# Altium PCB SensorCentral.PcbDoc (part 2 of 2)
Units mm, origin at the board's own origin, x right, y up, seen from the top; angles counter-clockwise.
Board outline 99.21 x 99.07 mm, 6 copper layers (Top Layer 1, GND1, Signal, GND2, GND3, Bottom Layer 1), stack 1.538 mm thick; 91 components, 67 nets, 452 pads, 462 vias.
Unrouted connection lines stored in the file: 278.
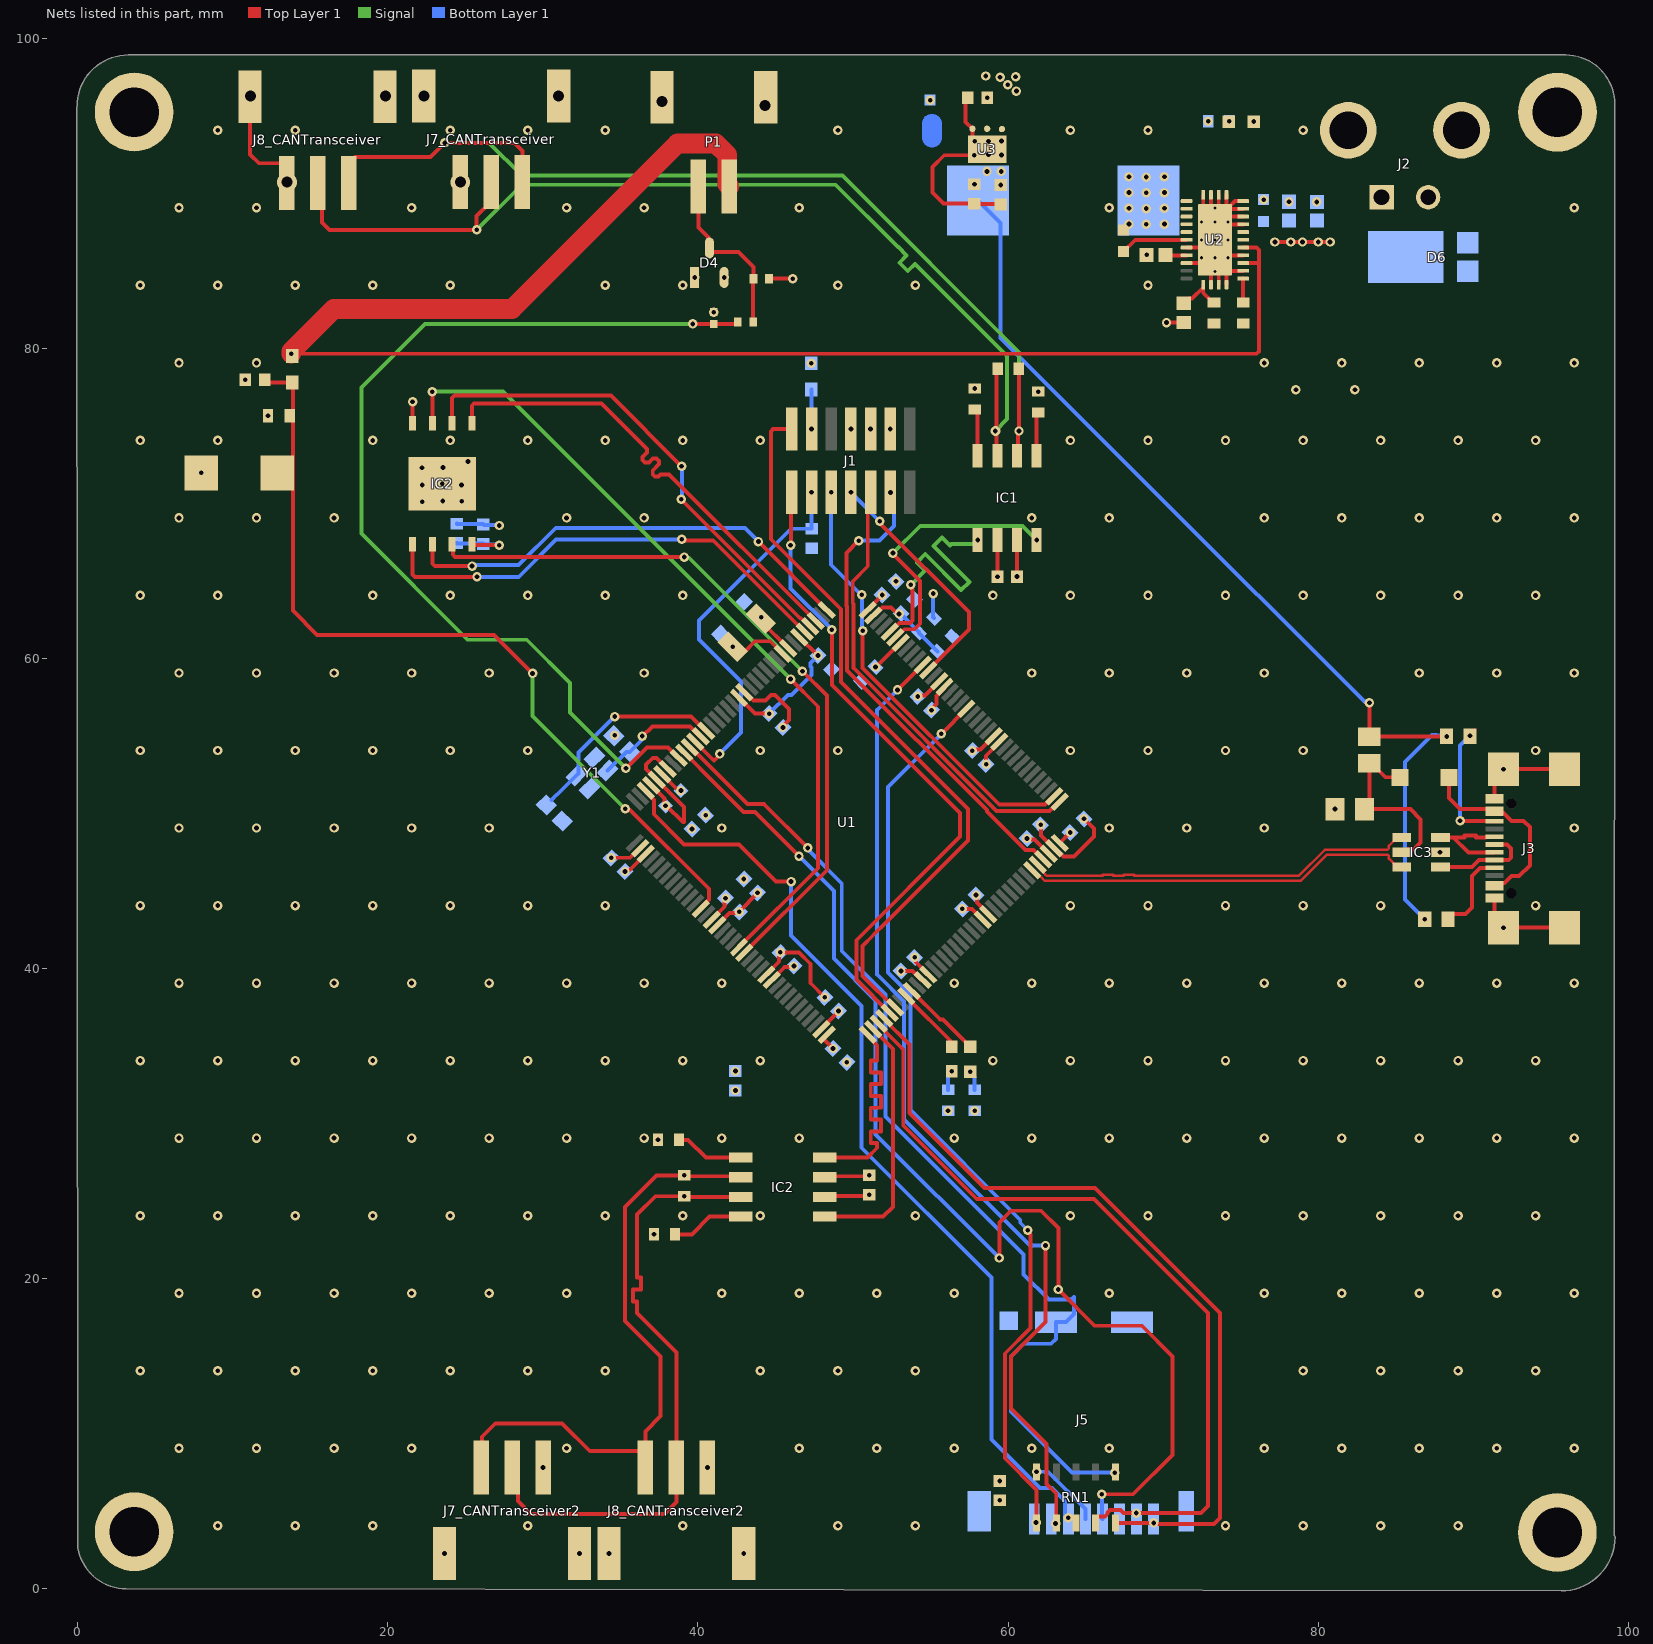
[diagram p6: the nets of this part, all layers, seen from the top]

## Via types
v1: diameter 0.61, hole 0.305, Top Layer 1 to Bottom Layer 1, tented both sides, 441 vias
v2: diameter 0.5, hole 0.2, Top Layer 1 to Bottom Layer 1, 11 vias
v3: diameter 1.27, hole 0.711, Top Layer 1 to Bottom Layer 1, tented both sides, 8 vias
v4: diameter 0.61, hole 0.33, Top Layer 1 to Bottom Layer 1, tented both sides, 1 vias
v5: diameter 0.65, hole 0.305, Top Layer 1 to Bottom Layer 1, tented both sides, 1 vias

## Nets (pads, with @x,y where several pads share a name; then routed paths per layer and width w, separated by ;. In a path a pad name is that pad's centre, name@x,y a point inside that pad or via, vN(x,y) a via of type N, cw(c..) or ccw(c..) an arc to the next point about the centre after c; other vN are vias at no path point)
5V: C8.1 D7.1 FB1.2 IC3.5 | length 11.9
  Top Layer 1 w0.254: FB1.2@83.312,53.252 83.312,50.612 C8.1@82.992,50.292 85.952,50.292 86.614,49.63 86.614,48.128 86.16,47.674 85.56,47.674 IC3.5@85.395,47.508 ; FB1.2@83.437,53.252 84.347,52.342 D7.1@85.007,52.342
ADC1_INP2: C36.1 D5.1 R12.1 R13.2 U1.49 | length 55.5
  Top Layer 1 w0.254: C36.1@12.057,77.978 12.23,77.805 13.937,77.805 13.944,77.797 13.868,77.721 13.868,72.984 D5.1@12.864,71.98 ; D5.1@13.876,73.011 13.876,63.095 15.442,61.53 26.843,61.53 v1(29.332,59.041) ; v1(35.307,50.313) 35.375,50.245 35.607,50.245 40.699,45.153 40.699,44.453 40.17,43.924 U1.49@40.17,43.862
  Signal w0.254: v1(29.332,59.041) 29.332,56.289 v1(35.307,50.313)
AN_P_PRESSURE_NOSE: C7.1 R8.2 U1.28 | length 64.1
  Top Layer 1 w0.254: v1(35.353,52.917) 36.712,54.276 38.065,54.276 U1.28@38.756,53.585 ; v1(39.672,81.582) C7.1@41.027,81.582 42.436,81.582 R8.2@42.559,81.706 R8.2@42.559,81.706
  Signal w0.254: v1(35.353,52.917) 31.75,56.52 31.75,58.42 28.956,61.214 25.146,61.214 18.288,68.072 18.288,77.47 22.4,81.582 v1(39.672,81.582)
BOOT0: R2.2 U1.138 | length 2.3
  Top Layer 1 w0.254: v1(51.455,59.456) 51.489,59.456 53.042,61.009 U1.138@53.075,61.009
CANH_CANTransceiver: IC1.7 J7_CANTransceiver.2 J8_CANTransceiver.2 R16.1 | length 68.6
  Top Layer 1 w0.254: J8_CANTransceiver.2@15.494,90.73 15.748,90.476 15.748,88.138 16.236,87.65 v1(25.728,87.65) 25.728,88.538 26.67,89.48 J7_CANTransceiver.2@26.67,90.73 ; IC1.7@59.309,73.07 59.245,73.134 59.245,74.612 v5(59.182,74.676) 59.258,74.752 59.258,78.619 R16.1@59.334,78.695
  Signal w0.254: v1(25.728,87.65) 28.639,90.561 48.885,90.561 52.826,86.62 52.916,86.53 52.925,86.539 53.463,86 52.992,85.528 53.531,84.99 53.993,85.453 54.149,85.297 59.944,79.502 59.944,75.438 v5(59.182,74.676)
CANH_CANTransceiver2: IC2.7@42.754,25.273 J7_CANTransceiver2.2 J8_CANTransceiver2.2 R16_CANTransceiver2.1 | length 41
  Top Layer 1 w0.254: J7_CANTransceiver2.2@28.008,7.822 28.381,7.449 28.381,5.655 29.21,4.826 37.846,4.826 38.608,5.588 J8_CANTransceiver2.2@38.608,7.822 38.608,15.24 36.068,17.78 36.068,18.415 36.068,18.542 35.814,18.542 35.814,19.304 36.32,19.304 36.32,20.066 36.068,20.066 36.068,20.442 36.068,24.13 37.255,25.317 v1(39.116,25.317) 39.16,25.273 IC2.7@42.754,25.273
CANL_CANTransceiver: IC1.6 J7_CANTransceiver.3 J8_CANTransceiver.3 R16.2 | length 68.6
  Top Layer 1 w0.254: J8_CANTransceiver.3@17.494,90.73 17.494,91.98 17.867,92.353 22.76,92.353 v1(23.663,93.256) 28.156,93.256 28.67,92.742 J7_CANTransceiver.3@28.67,90.73 ; IC1.6@60.579,73.07 60.642,73.134 60.642,74.612 v1(60.706,74.676) 60.697,74.685 60.697,78.686 R16.2@60.688,78.695
  Signal w0.254: v1(23.663,93.256) 26.535,93.256 28.646,91.145 49.317,91.145 60.706,79.756 v1(60.706,74.676)
CANL_CANTransceiver2: IC2.6@42.754,26.543 J7_CANTransceiver2.3 J8_CANTransceiver2.3 R16_CANTransceiver2.2 | length 41
  Top Layer 1 w0.254: J7_CANTransceiver2.3@26.008,7.822 26.06,7.874 26.06,9.804 26.924,10.668 31.242,10.668 33.02,8.89 36.235,8.89 36.608,8.517 J8_CANTransceiver2.3@36.608,7.822 36.608,10.157 37.592,11.141 37.592,14.986 35.306,17.272 35.306,24.638 37.338,26.67 v1(39.116,26.67) 39.179,26.606 42.69,26.606 IC2.6@42.754,26.543
CARD_DETECT: J5.10 RN1.6 U1.26 | length 66.4
  Top Layer 1 w0.254: U1.26@39.463,54.292 39.525,54.292 43.192,50.625 44.246,50.625 v1(47.087,47.783)
  Bottom Layer 1 w0.254: v1(47.087,47.783) 47.087,47.687 49.276,45.498 49.276,41.148 52.094,38.33 52.094,30.459 61,21.553 61,20.28 62.633,18.647 64.074,18.647 64.262,18.835 64.262,17.723 63.738,17.199 J5.10@63.088,17.199 63.088,16.118 62.774,15.804 61.011,15.804 60.198,14.991 60.198,11.43 64.139,7.489 v1(66.882,7.489)
CC1: J3.A5 R18.2 | length 5.6
  Top Layer 1 w0.254: R18.2@88.38,43.18 88.38,43.221 88.678,43.519 89.493,43.519 89.916,43.942 89.916,45.974 90.444,46.502 J3.A5@91.381,46.502
CC2: J3.B5 R19.1 | length 8.5
  Top Layer 1 w0.254: v1@89.155,49.529 90.809,49.529 90.813,49.525 91.356,49.525 J3.B5@91.38,49.501 ; R19.1@89.789,54.977 89.789,55.052 R19.1@90.087,55.35
  Bottom Layer 1 w0.254: v1(89.154,49.53) 89.154,54.379 v1(89.789,55.015)
CD/DAT3: J5.2 RN1.2 U1.134 | length 63.8
  Top Layer 1 w0.254: v1(52.869,57.975) U1.134@54.489,59.595 ; v1(62.417,22.138) 62.417,17.211 60.198,14.991 60.198,11.63 62.489,9.339 62.489,6.759 63.11,6.137 63.11,4.256 v1(63.066,4.212)
  Bottom Layer 1 w0.254: v1(52.869,57.975) 51.562,56.669 51.562,39.612 53.289,37.886 53.289,30.277 61.428,22.138 v1(62.417,22.138)
CL_PRESSURE_NOSE: D4.3 P1.2 R8.1 R17.1 | length 10.9
  Top Layer 1 w0.254: P1.2@40.027,90.194 40.027,87.812 40.677,87.162 40.677,86.544 D4.3@40.738,86.483 ; D4.3@40.738,86.365 40.885,86.218 42.612,86.218 43.575,85.254 R17.1@43.575,84.5 ; R17.1@43.55,84.5 43.55,83.289 43.559,83.28 R8.1@43.559,81.706
CLK: J5.5 U1.27 | length 75
  Top Layer 1 w0.254: U1.27@39.11,53.938 40.157,52.891 40.157,52.875 42.934,50.098 43.671,50.098 v1(46.517,47.252) ; v1(59.436,21.336) 59.436,23.622 60.198,24.384 62.127,24.384 63.246,23.265 v1(63.246,19.304) 65.583,16.967 68.631,16.967 70.612,14.986 70.612,8.636 68.072,6.096 v1(66.04,6.096)
  Bottom Layer 1 w0.254: v1(46.517,47.252) 48.768,45.001 48.768,40.64 51.46,37.948 51.46,29.312 v1(59.436,21.336) ; v1(66.04,6.096) 66.064,6.072 66.064,4.523 J5.5@66.088,4.499
CMD: J5.3 RN1.3 U1.34 | length 62
  Top Layer 1 w0.254: U1.34@36.635,51.464 36.635,51.401 37.163,50.873 37.163,49.959 39.108,48.014 42.644,48.014 45.042,45.616 v1(46.007,45.616) ; v1(63.882,4.58) 64.282,4.58 64.38,4.482 RN1.3@64.38,4.247
  Bottom Layer 1 w0.254: v1(46.007,45.616) 46.007,42.131 50.546,37.592 50.546,28.448 58.928,20.066 58.928,9.633 61.255,7.307 61.255,7.304 61.598,6.961 61.6,6.961 62.072,6.489 62.833,6.489 63.665,5.656 63.665,4.797 v1(63.882,4.58)
CS: IC2.1@25.412,75.176 U1.3 | length 31.4
  Top Layer 1 w0.254: IC2.1@25.412,75.176 25.412,76.305 25.561,76.454 33.782,76.454 36.725,73.511 36.725,73.301 36.427,73.003 36.427,72.793 36.576,72.644 36.83,72.644 37.084,72.898 37.338,72.898 37.487,72.749 37.487,72.539 37.084,72.136 37.084,71.882 37.233,71.733 37.443,71.733 37.592,71.882 38.136,71.882 47.533,62.486 U1.3@47.595,62.486
DAT0: J5.7 RN1.4 U1.75 | length 52.4
  Top Layer 1 w0.254: U1.75@51.661,36.437 51.661,36.375 53.24,34.796 53.24,29.89 57.984,25.146 65.532,25.146 72.898,17.78 72.898,5.334 72.449,4.885 v1(68.277,4.885) 67.455,4.885 67.262,5.078 66.579,5.078 66.414,4.913 66.414,4.839 66.245,4.67 65.748,4.67 65.65,4.572 RN1.4@65.65,4.247
DAT1: J5.8 RN1.5 U1.76 | length 52.3
  Top Layer 1 w0.254: U1.76@52.014,36.791 52.014,36.729 53.648,35.095 53.648,30.68 58.481,25.847 65.598,25.847 73.66,17.784 73.66,4.572 73.279,4.191 69.451,4.191 v1(69.395,4.247) RN1.5@66.92,4.247
DAT2: J5.1 RN1.1 U1.126 | length 60
  Top Layer 1 w0.254: v1(55.7,55.145) 55.7,55.147 57.318,56.764 U1.126@57.318,56.767 ; v1(61.273,23.121) 61.273,23.025 61.455,22.844 61.455,16.825 59.79,15.16 59.79,8.425 61.84,6.375 61.84,4.308 v1(61.807,4.275)
  Bottom Layer 1 w0.254: v1(55.7,55.145) 53.726,53.171 53.71,53.171 52.259,51.72 52.259,39.744 53.697,38.307 53.697,30.873 60.786,23.783 60.786,23.608 v1(61.273,23.121)
DCREG5V0: C18.1 C37.1 C38.1 FB1.1 L2.2 R9.2 R10.1 R18.1 R19.2 U3.5 U3.6 | length 65.7
  Top Layer 1 w0.254: v1(59.522,90.546) C37.1@59.549,90.546 ; R9.2@73.005,81.417 73.207,81.619 R9.2@73.284,81.619 ; v1(83.312,57.15) 83.312,55.002 83.337,54.977 v1(88.289,54.977)
  Bottom Layer 1 w0.254: C18.1@54.974,94.618 C18.1@55.099,94.493 ; L2.2@58.069,89.549 59.522,88.095 59.522,80.686 69.202,71.005 82.99,57.218 83.244,57.218 v1(83.312,57.15) ; v1(86.88,43.18) 85.598,44.462 85.598,53.34 87.338,55.08 87.592,55.08 87.626,55.045 88.221,55.045 v1(88.289,54.977)
  Bottom Layer 1 w1.27: 55.099,93.613 C18.1@55.099,94.493
  other v1: 57.833,90.593 58.642,91.417 59.563,91.417
DN: IC3.1 J3.A7 J3.B7 | length 6.6
  Top Layer 1 w0.254: IC3.1@87.864,46.548 89.913,46.548 90.367,47.002 92.291,47.002 92.44,47.151 92.44,47.755 92.193,48.002 J3.A7@91.381,48.002
DP: IC3.3 J3.A6 J3.B6 | length 6.5
  Top Layer 1 w0.254: IC3.3@88.15,48.471 88.717,48.471 ; J3.A6@91.381,47.502 89.686,47.502 88.717,48.471 ; J3.B6@91.381,48.502 91.358,48.479 90.813,48.479 90.805,48.471 90.658,48.471 90.19,48.471 90.19,48.58 89.428,48.58 89.428,48.471 89.301,48.471 88.717,48.471
FB: R9.1 R11.1 U2.12 | length 3.3
  Top Layer 1 w0.254: R11.1@71.334,82.922 71.634,83.222 71.874,83.222 72.59,83.938 U2.12@72.59,84.109 72.592,84.107 72.592,83.588 73.207,82.973 R9.1@73.284,82.973
FDCAN1_RX: IC1.4 U1.139 | length 17.6
  Top Layer 1 w0.254: v1(52.578,66.802) 52.578,66.75 54.315,65.013 54.315,62.246 53.961,61.892 53.312,61.892 52.784,61.363 U1.139@52.721,61.363
  Signal w0.254: v1(52.578,66.802) 54.338,68.562 60.933,68.562 v1(61.849,67.646)
FDCAN1_TX: IC1.1 U1.140 | length 17.6
  Top Layer 1 w0.254: U1.140@52.368,61.717 52.43,61.717 53.003,62.289 53.133,62.289 53.143,62.3 53.664,62.3 53.83,62.466 53.83,64.427 53.798,64.46 53.798,64.686 v1(53.729,64.754)
  Signal w0.254: v1(53.729,64.754) 54.554,65.579 54.644,65.668 54.121,66.191 54.66,66.73 56.978,64.411 57.517,64.95 55.198,67.269 55.737,67.808 56.26,67.285 56.367,67.392 57.712,67.392 57.966,67.646 v1(58.039,67.646)
FDCAN2_RX: IC2.4@48.178,27.813 U1.73 | length 15.9
  Top Layer 1 w0.254: IC2.4@48.178,27.813 50.927,27.813 51.562,28.448 51.562,28.612 51.562,28.739 51.146,28.739 51.146,29.501 51.793,29.501 51.793,30.263 51.146,30.263 51.146,31.025 51.793,31.025 51.793,31.787 51.146,31.787 51.146,32.549 51.793,32.549 51.793,33.311 51.146,33.311 51.146,34.073 51.562,34.073 51.562,34.249 51.562,35.054 50.954,35.663 U1.73@50.954,35.73
FDCAN2_TX: IC2.1@48.178,24.003 U1.74 | length 15.9
  Top Layer 1 w0.254: 48.941,24.003 51.943,24.003 52.578,24.638 52.578,34.813 U1.74@51.307,36.084
FLASH_RESET: IC2.7@24.142,67.376 U1.57 | length 47.4
  Top Layer 1 w0.254: IC2.7@24.142,67.376 24.194,67.324 24.194,66.697 24.342,66.548 v1(39.116,66.548) ; U1.57@42.999,41.034 48.309,46.344 48.309,57.609 v1(46.736,59.182)
  Signal w0.254: v1(39.116,66.548) 39.184,66.48 39.438,66.48 v1(46.736,59.182)
FLASH_WP: IC2.3@22.872,75.176 U1.56 | length 53
  Top Layer 1 w0.254: v1(22.86,77.216) 22.866,77.21 22.866,75.182 IC2.3@22.872,75.176 ; U1.56@42.645,41.387 47.757,46.499 47.757,56.891 v1(45.974,58.674)
  Signal w0.254: v1(22.86,77.216) 27.432,77.216 v1(45.974,58.674)
GND: C1.2 C2.2 C3.2 C4.2 C5.2 C6.2 C7.2 C8.2 C11.2 C13.2 C14.2 C15.2 C16.2 C18.2 C19.2 C20.2 C21.2 C22.2 C23.2 C24.2 C25.1 C26.2 C27.2 C28.2 C29.2 C30.2 C31.2 C32.2 C33.2 C34.2 C35.2 C36.2 C37.2 C38.2 C39.2 C46.2 C46_CANTransceiver2.2 C47.2 C48.2 C71.2 D5.2 IC1.2 IC2.2@48.178,25.273 IC2.4@21.602,75.176 IC2.9 IC3.2 J1.5 J1.7 J2.2 J2.3 J2.4 J3.A1_B12 J3.B1_A12 J3.SH1 J3.SH2 J3.SH3 J3.SH4 J5.6 J5.9 J5.11 J5.12 J5.13 J7_CANTransceiver2.1 J7_CANTransceiver2.4 J7_CANTransceiver2.5 J7_CANTransceiver.1 J7_CANTransceiver.4 J7_CANTransceiver.5 J8_CANTransceiver2.1 J8_CANTransceiver2.4 J8_CANTransceiver2.5 J8_CANTransceiver.1 J8_CANTransceiver.4 J8_CANTransceiver.5 P1.MP1 P1.MP2 pad.2 R2.1 R3.1 R4.1 R5.1 R6.1 R7.1 R11.2 R13.1 R14.2 R14_CANTransceiver2.2 R15.1 R15_CANTransceiver2.1 R17.2 U1.16 U1.31 U1.38 U1.51 U1.61 U1.83 U1.94 U1.107 U1.120 U1.130 U2.7 U2.9 U2.13 U2.14 U2.15 U2.17 U2.19 U2.23 U2.24 U2.25 U2.26 U2.27 U2.28 U2.29 U2.30 U2.31 U3.3 U3.7 Y1.2 Y1.4 | length 93
  Top Layer 1 w0.254: J8_CANTransceiver.4@11.112,96.228 11.112,92.52 11.684,91.948 13.089,91.948 13.462,91.575 J8_CANTransceiver.1@13.462,90.678 ; v1(21.595,76.557) 21.595,75.182 IC2.4@21.602,75.176 ; J7_CANTransceiver.1@24.638,90.698 v3(24.67,90.73) ; v1(34.407,47.15) 35.618,47.15 36.219,47.751 U1.38@36.281,47.751 ; U1.31@37.695,52.524 38.665,51.555 38.832,51.555 v1(38.9,51.487) ; U1.51@40.877,43.155 41.712,43.99 41.712,44.48 v1(41.78,44.548) ; U1.16@42.999,57.827 43.061,57.827 43.589,57.299 44.345,57.299 44.704,57.658 44.958,57.658 45.869,56.747 45.869,56.043 45.482,55.656 v1(45.482,55.56) ; U1.61@44.413,39.619 45.237,40.444 45.237,40.982 v1(45.305,41.05) 46.507,41.05 47.273,40.284 47.273,39.055 v1(48.179,38.149) ; R17.2@44.575,84.5 v1(46.107,84.5) ; IC2.2@48.178,25.273 48.25,25.345 50.982,25.345 v1(51.054,25.416) ; v1(53.095,39.841) 53.851,39.841 54.427,39.266 U1.83@54.489,39.266 ; v1(55.066,56.668) 55.066,56.764 55.375,57.073 55.375,57.59 55.903,58.119 U1.130@55.903,58.181 ; v1(57.052,43.858) 57.675,43.858 U1.94@58.378,43.155 ; C39.2@57.397,96.176 57.266,96.044 57.266,94.611 U3.3@57.705,94.172 57.705,93.517 v1(57.857,93.364) ; v1(57.819,92.461) 55.885,92.461 55.118,91.694 55.118,90.065 55.844,89.339 C38.2@57.833,89.339 57.856,89.315 59.499,89.315 C37.2@59.522,89.292 ; v1(58.587,53.174) 58.587,53.731 59.439,54.583 U1.120@59.439,54.645 ; IC1.2@59.309,67.646 59.313,67.642 v1(59.313,65.282) C46.2@59.317,65.278 ; v1(62.103,49.279) 62.133,49.249 62.133,48.593 U1.107@62.974,47.751 63.037,47.751 63.565,47.223 64.241,47.223 65.532,48.514 65.532,49.029 v1(64.895,49.666) ; v1(70.222,81.67) R11.2@71.334,81.67 ; U2.9@71.515,85.509 72.367,85.509 U2.31@72.598,85.74 ; U2.7@71.515,86.509 72.84,86.509 v2(73.34,87.009) ; U2.31@72.59,88.169 U2.30@72.59,89.909 ; U2.13@73.09,84.109 73.09,84.836 73.213,84.959 v2(73.34,84.959) ; U2.29@73.09,89.909 73.09,89.182 U2.31@73.213,89.059 ; U2.31@73.467,89.059 73.59,89.182 U2.28@73.59,89.909 ; U2.14@73.59,84.109 U2.31@73.59,85.732 ; U2.31@74.031,88.227 74.313,88.509 U2.24@75.165,88.509 ; U2.15@74.09,84.109 74.09,85.232 74.313,85.009 U2.17@75.165,85.009 ; U2.27@74.09,89.909 74.09,89.039 74.17,89.039 74.638,89.507 75.163,89.507 U2.26@75.165,89.509 ; U2.31@74.12,89.009 U2.25@75.165,89.009 ; U2.31@74.19,85.886 74.313,86.009 U2.19@75.165,86.009 ; v2(74.19,88.169) 74.19,88.132 74.313,88.009 U2.23@75.165,88.009 ; J3.A1_B12@91.381,44.552 91.381,43.217 v1(91.956,42.642) J3.SH3@95.886,42.642 ; J3.B1_A12@91.381,50.952 91.386,50.957 91.386,52.292 v1(91.956,52.862) J3.SH4@95.886,52.862 ; pad.2@95.435,95.238 pad.2@95.457,95.216
  Bottom Layer 1 w0.254: C48.2@24.444,68.699 24.47,68.674 26.126,68.674 26.186,68.614 27.144,68.614 v1(27.178,68.58)
  other v1: 23.658,2.272 32.358,2.272 34.258,2.272 42.958,2.272 9.026,4.069 14.026,4.069 19.026,4.069 29.026,4.069 39.026,4.069 49.026,4.069 54.026,4.069 74.026,4.069 79.026,4.069 84.026,4.069 89.026,4.069 59.473,6.958 30.008,7.822 40.608,7.822 6.526,9.069 11.526,9.069 16.526,9.069 21.526,9.069 31.526,9.069 46.526,9.069 51.526,9.069 56.526,9.069 61.526,9.069 66.526,9.069 76.526,9.069 81.526,9.069 86.526,9.069 91.526,9.069 96.526,9.069 4.026,14.069 9.026,14.069 14.026,14.069 19.026,14.069 24.026,14.069 29.026,14.069 34.026,14.069 44.026,14.069 49.026,14.069 54.026,14.069 79.026,14.069 84.026,14.069 89.026,14.069 94.026,14.069 6.526,19.069 11.526,19.069 16.526,19.069 21.526,19.069 26.526,19.069 31.526,19.069 41.526,19.069 46.526,19.069 51.526,19.069 56.526,19.069 66.526,19.069 76.526,19.069 81.526,19.069 86.526,19.069 91.526,19.069 96.526,19.069 37.169,22.86 4.026,24.069 9.026,24.069 14.026,24.069 19.026,24.069 24.026,24.069 29.026,24.069 34.026,24.069 39.026,24.069 44.026,24.069 54.026,24.069 64.026,24.069 69.026,24.069 74.026,24.069 79.026,24.069 84.026,24.069 89.026,24.069 94.026,24.069 37.423,28.956 6.526,29.069 11.526,29.069 16.526,29.069 21.526,29.069 26.526,29.069 31.526,29.069 36.526,29.069 41.526,29.069 46.526,29.069 56.526,29.069 61.526,29.069 66.526,29.069 71.526,29.069 76.526,29.069 81.526,29.069 86.526,29.069 91.526,29.069 96.526,29.069 56.134,30.831 57.847,30.831 42.418,33.393 49.6,33.961 4.026,34.069 9.026,34.069 14.026,34.069 19.026,34.069 24.026,34.069 29.026,34.069 34.026,34.069 39.026,34.069 44.026,34.069 59.026,34.069 64.026,34.069 69.026,34.069 74.026,34.069 79.026,34.069 84.026,34.069 89.026,34.069 94.026,34.069 6.526,39.069 11.526,39.069 16.526,39.069 21.526,39.069 26.526,39.069 31.526,39.069 36.526,39.069 41.526,39.069 56.526,39.069 61.526,39.069 66.526,39.069 71.526,39.069 76.526,39.069 81.526,39.069 86.526,39.069 91.526,39.069 96.526,39.069 4.026,44.069 9.026,44.069 14.026,44.069 19.026,44.069 24.026,44.069 29.026,44.069 34.026,44.069 64.026,44.069 69.026,44.069 74.026,44.069 79.026,44.069 84.026,44.069 94.026,44.069 42.961,45.779 87.864,47.498 6.526,49.069 11.526,49.069 16.526,49.069 21.526,49.069 26.526,49.069 41.526,49.069 66.526,49.069 71.526,49.069 76.526,49.069 96.526,49.069 40.497,49.895 81.092,50.292 4.026,54.069 9.026,54.069 14.026,54.069 19.026,54.069 24.026,54.069 29.026,54.069 44.026,54.069 49.026,54.069 64.026,54.069 69.026,54.069 74.026,54.069 79.026,54.069 94.026,54.069 34.632,55.045 6.526,59.069 11.526,59.069 16.526,59.069 21.526,59.069 26.526,59.069 36.526,59.069 61.526,59.069 66.526,59.069 71.526,59.069 76.526,59.069 86.526,59.069 91.526,59.069 96.526,59.069 4.026,64.069 9.026,64.069 19.026,64.069 24.026,64.069 29.026,64.069 34.026,64.069 39.026,64.069 59.026,64.069 64.026,64.069 69.026,64.069 74.026,64.069 79.026,64.069 84.026,64.069 89.026,64.069 94.026,64.069 52.766,64.984 6.526,69.069 11.526,69.069 16.526,69.069 31.526,69.069 36.526,69.069 61.526,69.069 66.526,69.069 76.526,69.069 81.526,69.069 86.526,69.069 91.526,69.069 96.526,69.069 22.221,70.114 24.772,70.147 23.535,70.164 22.212,71.198 24.747,71.198 23.507,71.276 7.964,71.98 22.204,72.3 23.551,72.317 25.171,72.707 4.026,74.069 9.026,74.069 19.026,74.069 24.026,74.069 29.026,74.069 34.026,74.069 39.026,74.069 44.026,74.069 64.026,74.069 69.026,74.069 74.026,74.069 79.026,74.069 84.026,74.069 89.026,74.069 94.026,74.069 49.864,74.802 51.134,74.802 12.269,75.659 61.954,77.216 78.566,77.339 82.376,77.339 57.855,77.414 10.803,77.978 47.315,79.047 6.526,79.069 11.526,79.069 76.526,79.069 81.526,79.069 86.526,79.069 91.526,79.069 96.526,79.069 41.027,82.339 4.026,84.069 9.026,84.069 14.026,84.069 19.026,84.069 24.026,84.069 34.026,84.069 39.026,84.069 49.026,84.069 54.026,84.069 69.026,84.069 68.943,86.038 6.526,89.069 11.526,89.069 21.526,89.069 31.526,89.069 36.526,89.069 46.526,89.069 66.526,89.069 96.526,89.069 78.122,89.463 79.92,89.453 76.488,89.599 59.58,92.481 58.741,92.506 58.741,93.364 59.574,93.377 9.026,94.069 14.026,94.069 24.026,94.069 29.026,94.069 34.026,94.069 49.026,94.069 64.026,94.069 69.026,94.069 79.026,94.069 72.911,94.664 54.974,96.018
  other v2: 72.49,85.849 73.34,85.849 74.19,85.849 72.49,87.009 74.19,87.009 72.49,88.169 73.34,88.169 73.34,89.059
  other v3: 13.494,90.73 44.329,95.676 37.677,95.944 11.144,96.28 19.844,96.28 22.32,96.28 31.02,96.28
MISO: IC2.2@24.142,75.176 U1.4 | length 32.3
  Top Layer 1 w0.254: IC2.2@24.142,75.176 24.142,76.813 24.291,76.962 34.383,76.962 v1(38.945,72.4) ; v1(38.914,70.276) 46.591,62.599 46.651,62.599 47.179,62.07 U1.4@47.241,62.07
  Bottom Layer 1 w0.254: v1(38.914,70.276) 38.976,70.338 38.976,72.369 v1(38.945,72.4)
MOSI: IC2.5@21.602,67.376 U1.5 | length 30.8
  Top Layer 1 w0.254: IC2.5@21.602,67.376 21.602,65.419 21.753,65.268 v1(25.748,65.268) ; v1(38.962,67.688) 39.03,67.62 39.281,67.62 39.282,67.619 40.985,67.619 U1.5@46.888,61.717
  Bottom Layer 1 w0.254: v1(25.748,65.268) 25.751,65.271 28.441,65.271 30.844,67.674 38.948,67.674 v1(38.962,67.688)
NetC11_1: C11.1 U2.8 | length 1.4
  Top Layer 1 w0.254: C11.1@70.144,86.038 70.174,86.009 U2.8@71.515,86.009
NetC12_1: C12.1 U2.6 | length 5.1
  Top Layer 1 w0.254: C12.1@67.442,86.246 68.204,87.009 U2.6@71.515,87.009 70.813,87.009
NetC12_2: C12.2 L2.1 U2.1 U2.2 U2.3 U2.4 U2.5
  other v1: 68.914,88.007 67.799,88.025 70.085,88.025 68.914,89.023 67.799,89.041 70.085,89.041 68.914,90.039 67.799,90.057 70.085,90.057 68.914,91.055 67.799,91.073 70.085,91.073
NetC21_1: C21.1 U1.71 | length 1.6
  Top Layer 1 w0.254: U1.71@47.948,36.084 47.948,36.114 49.066,37.232 v1(49.066,37.262)
NetC22_1: C22.1 U1.106 | length 1.8
  Top Layer 1 w0.254: v1(61.216,48.392) 61.284,48.324 61.694,48.324 U1.106@62.621,47.398
NetD1_1: D1.1 R5.2
  other v1: 74.265,94.664
NetD2_1: D2.1 R6.2 | length 1.3
  Bottom Layer 1 w0.254: R6.2@56.134,32.184 56.134,33.045 56.367,33.277 v1(56.367,33.373)
NetD3_1: D3.1 R4.2 | length 1.3
  Bottom Layer 1 w0.254: v1(57.566,33.353) 57.566,33.256 57.847,32.976 R4.2@57.847,32.184
NetD7_2: D7.2 J3.A4_B9 J3.B4_A9 | length 12.6
  Top Layer 1 w0.254: D7.2@88.443,52.324 88.443,51.003 89.154,50.292 91.713,50.292 92.475,49.53 93.256,49.53 93.655,49.131 93.655,46.665 92.964,45.974 92.475,45.974 92.026,45.525 91.554,45.525 J3.A4_B9@91.381,45.352
NetIC1_5: IC1.5 R15.2 | length 2.8
  Top Layer 1 w0.254: IC1.5@61.849,73.07 61.849,75.758 R15.2@61.954,75.863
NetIC1_8: IC1.8 R14.1 | length 3.1
  Top Layer 1 w0.254: R14.1@57.855,76.06 58.039,75.876 IC1.8@58.039,73.07
NetIC1_CANTransceiver2_5: IC2.5@42.754,27.813 R15_CANTransceiver2.2 | length 4.5
  Top Layer 1 w0.254: R15_CANTransceiver2.2@38.777,28.956 39.37,28.956 40.513,27.813 IC2.5@42.754,27.813
NetIC1_CANTransceiver2_8: IC2.8@42.754,24.003 R14_CANTransceiver2.1 | length 4.5
  Top Layer 1 w0.254: R14_CANTransceiver2.1@38.777,22.86 39.614,22.86 40.757,24.003 IC2.8@42.754,24.003
NetJ1_11: J1.11 R7.2 | length 2.5
  Bottom Layer 1 w0.254: R7.2@47.315,77.347 47.324,77.337 v1(47.324,74.802)
NetR10_2: R10.2 U2.16 | length 1.5
  Top Layer 1 w0.254: U2.16@75.165,84.509 75.165,82.992 R10.2@75.184,82.973
OTG_FS_N: IC3.6 U1.103 | length 25.2
  Top Layer 1 w0.161: U1.103@61.56,46.337 61.688,46.337 62.177,45.848 62.18,45.848 62.366,45.662 78.873,45.662 80.562,47.351 84.466,47.351 84.56,47.257 84.56,47.093 85.095,46.558 IC3.6@85.395,46.558
OTG_FS_P: IC3.4 U1.104 | length 25.2
  Top Layer 1 w0.161: U1.104@61.914,46.691 61.914,46.562 62.402,46.074 62.402,46.071 62.497,45.977 65.523,45.977 66.122,45.977 66.122,46.044 66.79,46.044 66.79,45.977 67.459,45.977 67.459,46.044 68.128,46.044 68.128,45.977 68.877,45.977 78.743,45.977 80.432,47.666 84.466,47.666 84.56,47.76 84.56,47.924 85.095,48.458 IC3.4@85.395,48.458
PD11: D2.2 U1.80 | length 4.4
  Top Layer 1 w0.254: U1.80@53.428,38.205 56.434,35.2 D2.2@56.623,35.2
PD12: D3.2 U1.81 | length 5.3
  Top Layer 1 w0.254: U1.81@53.782,38.559 55.625,36.715 55.804,36.715 D3.2@57.566,34.953
PDR_ON: C2.1 R1.2 R3.2 U1.143 | length 5.6
  Top Layer 1 w0.254: U1.143@51.307,62.777 51.369,62.777 51.898,63.306 52.443,63.306 52.874,62.875 v1(52.97,62.875)
  Bottom Layer 1 w0.254: v1(52.97,62.875) 53.048,62.875 C2.1@53.083,62.91 53.083,62.879 54.264,61.698 54.264,61.654 55.449,60.468 R3.2@55.449,60.455
SCK: IC2.6@22.872,67.376 U1.1 | length 30
  Top Layer 1 w0.254: IC2.6@22.872,67.376 22.872,66.113 23.022,65.962 v1(25.431,65.962) ; v1(43.898,67.547) 43.898,67.541 48.302,63.137 U1.1@48.302,63.131
  Bottom Layer 1 w0.254: v1(25.431,65.962) 25.497,66.029 28.437,66.029 30.828,68.42 43.026,68.42 v1(43.898,67.547)
T_JTDI: J1.10 U1.110 | length 28.5
  Top Layer 1 w0.254: v1(50.621,61.801) 50.621,59.395 59.435,50.581 62.384,50.581 62.912,51.11 U1.110@62.974,51.11
  Bottom Layer 1 w0.254: v1(48.594,70.732) 48.58,70.718 48.58,66.049 v1@50.514,64.115 ; v1(50.568,64.115) v1@50.514,64.115 ; v1(50.621,61.801) 50.594,61.828 50.594,64.034 v1@50.514,64.115
T_NRST: C1.1 J1.12 U1.25 | length 24.7
  Top Layer 1 w0.254: U1.25@39.817,54.645 39.817,54.633 41.042,53.408 41.402,53.768 v1(41.402,53.848)
  Bottom Layer 1 w0.254: v1(41.402,53.848) 42.788,55.234 42.788,58.507 40.06,61.235 40.06,62.446 45.988,68.374 47.318,68.374 47.324,68.38 v1(47.324,70.732)
T_SWCLK: J1.6 U1.109 | length 29.2
  Top Layer 1 w0.254: J1.6@51.134,70.732 50.953,70.551 50.953,65.954 49.982,64.983 49.982,63.57 50.035,63.518 50.035,59.404 59.266,50.173 62.683,50.173 63.266,50.756 U1.109@63.328,50.756
T_SWDIO: J1.4 U1.105 | length 31.5
  Top Layer 1 w0.254: v1(50.364,67.604) 49.574,66.814 49.574,63.401 49.627,63.349 49.627,59.235 58.632,50.23 58.632,50.148 61.115,47.664 61.644,47.664 62.265,47.044 U1.105@62.267,47.044 ; J1.4@52.343,70.793 J1.4@52.404,70.732
  Bottom Layer 1 w0.254: v1(50.364,67.604) 51.699,67.604 52.634,68.539 52.634,70.407 52.421,70.62 v1(52.421,70.716)
T_SWO: J1.8 U1.133 | length 15.7
  Top Layer 1 w0.254: v1(51.719,68.855) 51.787,68.787 51.787,68.685 57.482,62.989 57.482,61.881 U1.133@54.843,59.242
  Bottom Layer 1 w0.254: v1(49.864,70.732) 49.864,70.709 v1(51.719,68.855)
T_VCP_RX: J1.13 U1.78 | length 47.5
  Top Layer 1 w0.254: J1.13@46.054,74.802 44.853,74.802 44.704,74.653 44.704,67.695 49.219,63.18 49.219,58.477 57.404,50.292 57.404,48.26 52.193,43.049 51.308,42.164 51.308,42.152 50.621,41.465 50.621,39.536 52.659,37.498 U1.78@52.721,37.498
T_VCP_TX: J1.14 U1.77 | length 41.8
  Top Layer 1 w0.254: v1(45.974,67.31) 46.014,67.35 46.014,70.692 J1.14@46.054,70.732 ; v1(48.633,61.858) 48.635,61.857 48.635,58.299 56.896,50.038 56.896,48.514 50.213,41.831 50.213,39.299 U1.77@52.368,37.145
  Bottom Layer 1 w0.254: v1(45.974,67.31) 45.974,64.523 48.633,61.864 v1(48.633,61.858)
VBAT: C13.1 C14.1 C15.1 D6.3 P1.1 R12.2 U2.18 U2.20 U2.21 U2.22 | length 110.5
  Top Layer 1 w0.254: v1(13.767,79.66) 76.027,79.66 76.176,79.809 76.176,86.36 76.027,86.509 U2.20@75.165,86.509 ; U2.18@75.413,85.511 75.461,85.511 75.465,85.515 76.05,85.515 ; v1(77.216,86.868) v1(78.232,86.868) v1(78.994,86.868) v1(80.01,86.868) v1(80.772,86.868)
  Top Layer 1 w1.27: v1(13.767,79.66) 13.767,79.807 16.51,82.55 28.009,82.55 38.677,93.218 41.148,93.218 41.892,92.474 41.892,90.583 P1.1@42.027,90.448
VBAT_IN: D6.1 D6.2 J2.1
VDD: C16.1 C19.1 C20.1 C23.1 C24.1 C25.2 C26.1 C27.1 C28.1 C29.1 C30.1 C31.1 C32.1 C33.1 C34.1 C35.1 C39.1 C46.1 C46_CANTransceiver2.1 C47.1 C48.1 C71.1 D1.2 D4.1 D4.2 IC1.3 IC2.3@48.178,26.543 IC2.8@25.412,67.376 J1.3 J5.4 R1.1 RN1.10 U1.6 U1.17 U1.30 U1.32 U1.33 U1.39 U1.52 U1.62 U1.72 U1.84 U1.95 U1.108 U1.121 U1.131 U1.144 U3.1 U3.2 | length 52.8
  Top Layer 1 w0.254: IC2.8@25.412,67.376 25.477,67.31 v1(27.178,67.31) ; v1(35.294,46.263) 35.362,46.331 35.568,46.331 U1.39@36.635,47.398 ; U1.33@36.988,51.817 37.842,50.963 37.842,50.565 v1(37.91,50.497) 37.983,50.497 39.023,49.457 39.095,49.457 39.095,50.418 36.644,52.869 36.644,53.154 37.084,53.594 37.333,53.594 U1.30@38.049,52.878 ; D4.1@39.707,84.5 v1(39.788,84.582) ; U1.52@41.231,42.801 42.023,43.593 42.599,43.593 v1(42.667,43.661) 42.667,43.687 43.847,44.867 v1(43.847,44.893) ; U1.17@42.645,57.474 43.673,56.446 v1(44.595,56.446) ; U1.62@44.766,39.266 45.596,40.095 46.124,40.095 v1(46.192,40.163) ; U1.6@46.534,61.363 46.563,61.363 v1(47.736,60.191) ; IC2.3@48.178,26.543 48.242,26.606 50.99,26.606 v1(51.054,26.67) ; U1.72@48.302,35.73 48.1,35.529 48.1,35.461 v1(48.714,34.847) ; U1.144@50.954,63.131 50.954,63.151 51.88,64.077 v1(51.88,64.097) ; v1(53.982,40.728) 54.05,40.66 54.05,40.412 U1.84@54.843,39.619 ; v1(54.179,57.554) 54.247,57.622 54.638,57.622 U1.131@55.55,58.535 ; v1(57.7,54.061) 57.768,54.129 58.215,54.129 U1.121@59.085,54.999 ; v1(57.939,44.745) 58.007,44.677 58.007,44.277 58.732,43.552 U1.95@58.732,43.509 ; C46.1@60.571,65.278 v4(60.575,65.282) 60.575,67.642 IC1.3@60.579,67.646 ; U1.108@63.328,48.105 63.335,48.105 v1(64.009,48.779)
  Bottom Layer 1 w0.254: C48.1@24.444,67.445 24.47,67.42 26.126,67.42 26.194,67.352 27.136,67.352 v1(27.178,67.31) ; v1(44.595,56.446) 45.804,57.655 46.039,57.655 47.322,58.938 47.322,59.425 47.251,59.496 47.251,59.706 v1(47.736,60.191) ; v1(55.172,64.194) 55.167,64.188 55.167,62.678 R1.1@55.221,62.624 ; v1(61.84,7.547) 62.59,7.547 64.988,5.149 J5.4@64.988,4.499
  other v1: 59.473,5.704 42.418,32.139 39.61,49.008 52.404,74.802 41.688,84.582 75.84,94.638 58.651,96.176 60.542,96.601 59.987,97.013 59.485,97.495 60.485,97.519 58.567,97.575
XTAL1A: C5.1 U1.8 Y2.1 | length 2.7
  Top Layer 1 w0.254: v1(44.078,62.669) 44.078,62.405 U1.8@45.827,60.656
XTAL1B: C6.1 U1.9 Y2.2 | length 3.9
  Top Layer 1 w0.254: v1(42.253,60.77) 42.535,60.487 43.063,60.487 43.691,61.114 44.661,61.114 U1.9@45.474,60.302
XTAL2A: C3.1 U1.23 Y1.1 | length 13.3
  Top Layer 1 w0.254: v1(34.624,56.257) 39.557,56.257 40.462,55.353 U1.23@40.524,55.353
  Bottom Layer 1 w0.254: 30.56,50.89 30.884,51.215 30.914,51.215 Y1.1@32.172,52.473 32.296,52.597 32.296,53.929 v1(34.624,56.257)
XTAL2B: C4.1 U1.24 Y1.3 | length 7.6
  Top Layer 1 w0.254: v1(36.414,54.999) 36.432,54.999 37.059,55.626 39.481,55.626 40.108,54.999 U1.24@40.17,54.999
  Bottom Layer 1 w0.254: Y1.3@34.17,52.774 35.382,53.986 C4.1@35.602,53.986 36.346,54.731 36.346,54.931 v1(36.414,54.999)
pads on no net: J1.1 J1.2 J1.9 J3. J3.A8 J3.B8 RN1.7 RN1.8 RN1.9 U1.2 U1.7 U1.10 U1.11 U1.12 U1.13 U1.14 U1.15 U1.18 U1.19 U1.20 U1.21 U1.22 U1.29 U1.35 U1.36 U1.37 U1.40 U1.41 U1.42 U1.43 U1.44 U1.45 U1.46 U1.47 U1.48 U1.50 U1.53 U1.54 U1.55 U1.58 U1.59 U1.60 U1.63 U1.64 U1.65 U1.66 U1.67 U1.68 U1.69 U1.70 U1.79 U1.82 U1.85 U1.86 U1.87 U1.88 U1.89 U1.90 U1.91 U1.92 U1.93 U1.96 U1.97 U1.98 U1.99 U1.100 U1.101 U1.102 U1.111 U1.112 U1.113 U1.114 U1.115 U1.116 U1.117 U1.118 U1.119 U1.122 U1.123 U1.124 U1.125 U1.127 U1.128 U1.129 U1.132 U1.135 U1.136 U1.137 U1.141 U1.142 U2.10 U2.11 U3.4

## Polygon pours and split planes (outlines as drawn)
GND on Top Layer 1 "GND_L01_P052" (solid, pour order 52): -0.508,99.822 98.806,99.822 99.822,98.806 99.568,98.552 99.568,-1.778 1.524,-1.778 -0.508,0.254
DCREG5V0 on Top Layer 1 "NONET_L06_P-001" (solid, pour order 3): 57.427,90.972 57.757,90.972 58.569,91.784 59.691,91.784 70.702,80.772 71.701,80.772 72.878,81.949 75.59,81.949 75.59,80.162 75.438,80.01 75.184,80.264 60.452,80.264 60.452,89.148 59.882,89.718 57.427,89.718
VBAT on Top Layer 1 "VBAT_L01_P005" (solid, remove dead copper, pour order 5): 74.816,87.632 74.801,87.617 74.801,86.387 81.269,86.387 81.193,87.629 78.285,87.617
NetC12_2 on Top Layer 1 "NETC12_2_L01_P006" (solid, remove dead copper, pour order 6): 71.892,87.385 71.892,90.982 71.079,91.795 67.084,91.795 67.084,87.327 67.073,87.316
DCREG5V0 on Top Layer 1 "DCREG5V0_L01_P011" (solid, remove dead copper, pour order 11): 57.039,90.067 57.049,90.057 59.925,90.057 59.925,91.77 59.94,91.785 59.924,91.801 57.039,91.801
VDD on Top Layer 1 "VDD_L01_P025" (solid, remove dead copper, pour order 25): 58.161,94.099 58.147,94.113 58.147,98.439 61.449,98.439 61.449,93.867 58.409,93.867 58.12,94.155
GND on Bottom Layer 1 "Bottom Layer 1-GND" (solid, remove dead copper, pour order 50): 0.723,94.864 0.776,1.924 ccw(c3.906,2.459) 3.906,-0.716 96.451,-0.847 ccw(c96.451,2.632) 99.93,2.632 99.893,2.721 99.919,95.042 ccw(c96.743,95.042) 96.743,98.217 4.061,98.217 4.036,98.22 ccw(c4.036,94.915) 0.731,94.915
VBAT on Bottom Layer 1 "NONET_L06_P-001" (solid, pour order 4): 88.091,84.217 88.091,87.577 83.231,87.577 82.103,88.705 77.678,88.705 77.668,88.714 77.503,88.549 76.138,88.549 76.138,87.849 76.113,87.824 76.113,84.265 76.065,84.217
VBAT_IN on Bottom Layer 1 "NONET_L06_P-001" (solid, pour order 46): 82.529,90.932 92.71,90.932 93.726,89.916 93.726,82.804 88.705,82.804 88.283,83.226 88.283,87.893 82.661,87.893
DCREG5V0 on Bottom Layer 1 "DCREG" (solid, remove dead copper, pour order 49): 56.115,87.263 53.692,89.685 50.609,89.685 50.609,93.696 50.781,93.867 50.903,93.745 56.191,93.745
GND on GND2 "GND2-GND" (solid, remove dead copper, pour order 43): -0.055,95.576 -0.002,2.635 ccw(c3.128,3.171) 3.128,-0.004 95.673,-0.135 ccw(c95.673,3.344) 99.152,3.344 99.115,3.433 99.141,95.754 ccw(c95.965,95.754) 95.965,98.929 3.283,98.929 3.258,98.932 ccw(c3.258,95.627) -0.047,95.627
GND on GND1 "GND1-GND" (solid, remove dead copper, pour order 44): 0.377,95.755 0.431,2.815 ccw(c3.561,3.35) 3.561,0.175 96.105,0.044 ccw(c96.105,3.523) 99.584,3.523 99.548,3.612 99.573,95.933 ccw(c96.398,95.933) 96.398,99.108 3.716,99.108 3.69,99.111 ccw(c3.69,95.806) 0.385,95.806
GND on GND3 "GND3-GND" (solid, remove dead copper, pour order 45): -0.055,95.576 -0.002,2.635 ccw(c3.128,3.171) 3.128,-0.004 95.673,-0.135 ccw(c95.673,3.344) 99.152,3.344 99.115,3.433 99.141,95.754 ccw(c95.965,95.754) 95.965,98.929 3.283,98.929 3.258,98.932 ccw(c3.258,95.627) -0.047,95.627
VDD on Signal "Signal-3V3" (solid, remove dead copper, pour order 48): -0.055,95.576 -0.002,2.635 ccw(c3.128,3.171) 3.128,-0.004 95.673,-0.135 ccw(c95.673,3.344) 99.152,3.344 99.115,3.433 99.141,95.754 ccw(c95.965,95.754) 95.965,98.929 3.283,98.929 3.258,98.932 ccw(c3.258,95.627) -0.047,95.627

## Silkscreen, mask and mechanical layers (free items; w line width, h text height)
Top Overlay:
  drawing of 194 lines, arcs and shapes, not listed
  text "Pressure" at 48.514,97.282 h1.52 r270
  text "CAN1" at 13.208,86.106 h1.52
  text "CAN1" at 24.384,86.106 h1.52
  text "IC1" at 65.024,69.088 h1.52 r90
  text "USB-C" at 90.932,55.424 h1.52
  text "IC3" at 84.836,43.942 h1.22
  text "Sensor system (SS)" at 76.358,32.862 h2.54 r90
  text "IC2" at 43.18,20.574 h1.52
  text "CAN2" at 24.892,10.922 h1.52
  text "CAN2" at 35.306,10.922 h1.52
Board:
  lines w0.254: 0.072,2.739 0.072,95.576 ; 0.08,3.171 ccw(c3.128,3.171) 3.128,0.123 95.673,-0.008 ccw(c95.673,3.344) 99.025,3.344 ; 0.08,95.627 cw(c3.258,95.627) 3.258,98.805 ; 3.255,98.802 95.965,98.802 cw(c95.965,95.754) 99.013,95.754 98.988,3.298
